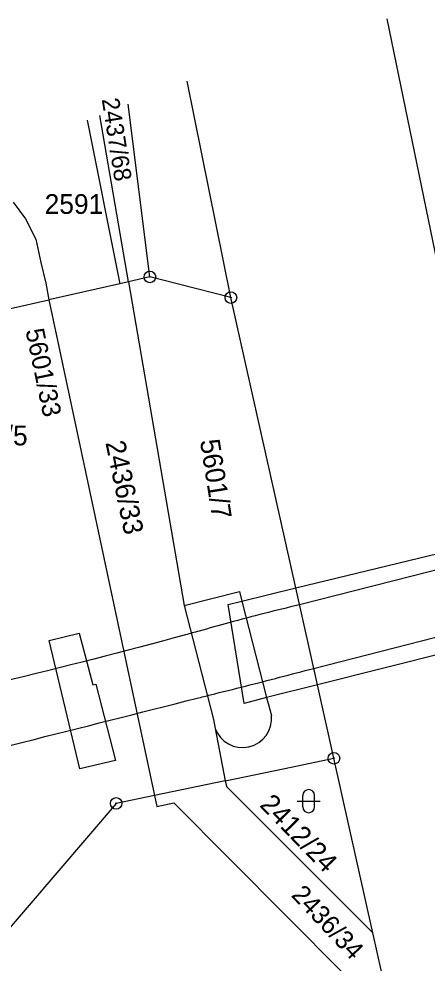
# Model space of a CAD drawing. Extents: x -825057 to -819383, y -1071633 to -1067888.
# Drawn here: x -820420.8 to -820385.6, y -1069607.9 to -1069526.4 of the extents above; entities that cross this region are included whole.
import ezdxf

# ---------------------------------------------------------------- set-up
doc = ezdxf.new("R2010")
doc.units = 0
for name, color, linetype in [('Vrstva 1', 7, 'Continuous'), ('Vrstva 10', 7, 'Continuous'), ('Vrstva 13', 7, 'Continuous'), ('Vrstva 16', 7, 'Continuous'), ('Vrstva 17', 7, 'Continuous'), ('Vrstva 18', 7, 'Continuous'), ('Vrstva 24', 7, 'Continuous'), ('Vrstva 25', 7, 'Continuous'), ('Vrstva 4', 7, 'Continuous')]:
    doc.layers.add(name, color=color, linetype=linetype)

msp = doc.modelspace()

# ---------------------------------------------------------------- linework, layer by layer
at = {"layer": 'Vrstva 1'}
for p, q in [((-820389.08, -1069526.4), (-820383.05, -1069555.68)), ((-820409.51, -1069548.66), (-820411.37, -1069533.75)), ((-820414.91, -1069535.15), (-820412.1, -1069549.25)), ((-820411.36, -1069549.08), (-820413.84, -1069534.72)), ((-820421.32, -1069542.21), (-820420.23, -1069543.65)), ((-820420.23, -1069543.65), (-820419.58, -1069544.95)), ((-820420.23, -1069543.65), (-820419.36, -1069545.39)), ((-820419.36, -1069545.39), (-820418.93, -1069547.42)), ((-820418.93, -1069547.42), (-820418.49, -1069549.19)), ((-820418.49, -1069549.19), (-820418.24, -1069550.64)), ((-820412.1, -1069549.25), (-820418.24, -1069550.64)), ((-820411.36, -1069549.08), (-820412.1, -1069549.25)), ((-820409.51, -1069548.66), (-820411.36, -1069549.08)), ((-820411.36, -1069549.08), (-820406.55, -1069577.01)), ((-820407.04, -1069549.29), (-820409.51, -1069548.66)), ((-820402.52, -1069550.44), (-820407.04, -1069549.29)), ((-820421.54, -1069551.39), (-820418.24, -1069550.64)), ((-820418.24, -1069550.64), (-820409.12, -1069593.39)), ((-820406.55, -1069577.01), (-820404.03, -1069586.83)), ((-820404.03, -1069586.83), (-820403.88, -1069587.6)), ((-820403.88, -1069587.6), (-820403.01, -1069592.12)), ((-820397.87, -1069591.06), (-820393.63, -1069590.18)), ((-820403.01, -1069592.12), (-820397.87, -1069591.06)), ((-820403.01, -1069592.12), (-820409.12, -1069593.39)), ((-820403.01, -1069592.12), (-820402.91, -1069592.61)), ((-820402.91, -1069592.61), (-820390.28, -1069605.24)), ((-820412.42, -1069594.07), (-820423.46, -1069606.97)), ((-820409.12, -1069593.39), (-820412.42, -1069594.07)), ((-820409.12, -1069593.39), (-820408.91, -1069594.35)), ((-820408.91, -1069594.35), (-820407.44, -1069594.03)), ((-820407.44, -1069594.03), (-820392.85, -1069608.7))]:
    msp.add_line(p, q, dxfattribs=at)
at = {"layer": 'Vrstva 10'}
for p, q in [((-820272.75, -1069545.33), (-820396.61, -1069576.94)), ((-820395.38, -1069582.43), (-820271.07, -1069550.51))]:
    msp.add_line(p, q, dxfattribs=at)
for points in [[(-820396.61, -1069576.94), (-820402.69, -1069578.49), (-820405.27, -1069579.21), (-820406.43, -1069579.53), (-820438.24, -1069587.5), (-820457.43, -1069592.39), (-820477.68, -1069597.79), (-820496.15, -1069603.16), (-820515.37, -1069609.41), (-820535.3, -1069616.98), (-820554.11, -1069625.3), (-820571.83, -1069634.26), (-820585.28, -1069641.81), (-820606.27, -1069655.04), (-820628.29, -1069671.01), (-820647.93, -1069687.34), (-820667.41, -1069705.6), (-820680.13, -1069718.49), (-820694.73, -1069734.03), (-820703.98, -1069744.22)], [(-820699.99, -1069747.07), (-820686.76, -1069732.45), (-820676.49, -1069721.48), (-820664.13, -1069708.83), (-820651.61, -1069696.85), (-820636.83, -1069683.83), (-820625.37, -1069674.56), (-820604.01, -1069659.07), (-820586.04, -1069647.64), (-820569.6, -1069638.45), (-820551.99, -1069629.79), (-820532.99, -1069621.67), (-820513.48, -1069614.48), (-820494.57, -1069608.43), (-820474.72, -1069602.78), (-820455.51, -1069597.69), (-820435.43, -1069592.58), (-820405.44, -1069585), (-820404.29, -1069584.71), (-820401.25, -1069583.95), (-820395.38, -1069582.43)]]:
    msp.add_spline(points, degree=3, dxfattribs=at)
at = {"layer": 'Vrstva 13'}
for p, q in [((-820402.52, -1069550.44), (-820406.29, -1069531.76)), ((-820396.93, -1069575.49), (-820402.52, -1069550.44)), ((-820395.06, -1069583.85), (-820396.93, -1069575.49)), ((-820393.63, -1069590.18), (-820395.06, -1069583.85)), ((-820390.28, -1069605.24), (-820393.63, -1069590.18)), ((-820389.54, -1069608.56), (-820390.28, -1069605.24))]:
    msp.add_line(p, q, dxfattribs=at)
at = {"layer": 'Vrstva 24'}
for centre, radius in [((-820409.51, -1069548.66), 0.5), ((-820409.51, -1069548.66), 0.0327), ((-820402.52, -1069550.44), 0.5), ((-820402.52, -1069550.44), 0.5), ((-820402.52, -1069550.44), 0.0327), ((-820402.52, -1069550.44), 0.0327), ((-820393.63, -1069590.18), 0.5), ((-820393.63, -1069590.18), 0.5), ((-820393.63, -1069590.18), 0.0327), ((-820393.63, -1069590.18), 0.0327), ((-820412.42, -1069594.07), 0.5), ((-820412.42, -1069594.07), 0.0327)]:
    msp.add_circle(centre, radius, dxfattribs=at)
at = {"layer": 'Vrstva 25'}
for p, q in [((-820396.81, -1069593.88), (-820394.81, -1069593.88)), ((-820396.31, -1069594.38), (-820396.31, -1069593.38)), ((-820395.31, -1069594.38), (-820395.31, -1069593.38))]:
    msp.add_line(p, q, dxfattribs=at)
for centre, start, end in [((-820395.81, -1069593.38), 0, 180), ((-820395.81, -1069594.38), 180, 0)]:
    msp.add_arc(centre, 0.5, start, end, dxfattribs=at)
at = {"layer": 'Vrstva 4'}
for p, q in [((-820396.93, -1069575.49), (-820379.33, -1069571.23)), ((-820406.55, -1069577.01), (-820401.79, -1069575.79)), ((-820401.79, -1069575.79), (-820401.57, -1069576.62)), ((-820401.57, -1069576.62), (-820396.93, -1069575.49)), ((-820402.75, -1069576.92), (-820401.57, -1069576.62)), ((-820401.38, -1069585.45), (-820402.75, -1069576.92)), ((-820401.57, -1069576.62), (-820399.44, -1069584.95)), ((-820418.19, -1069580.01), (-820415.61, -1069579.4)), ((-820415.61, -1069579.4), (-820414.44, -1069583.86)), ((-820377.38, -1069579.39), (-820395.06, -1069583.85)), ((-820415.54, -1069591.1), (-820418.19, -1069580.01)), ((-820414.44, -1069583.86), (-820414.16, -1069583.78)), ((-820414.16, -1069583.78), (-820412.48, -1069590.37)), ((-820395.06, -1069583.85), (-820399.44, -1069584.95)), ((-820399.44, -1069584.95), (-820401.38, -1069585.45)), ((-820399.44, -1069584.95), (-820399.03, -1069586.49)), ((-820412.48, -1069590.37), (-820415.54, -1069591.1))]:
    msp.add_line(p, q, dxfattribs=at)
msp.add_arc((-820401.524, -1069586.745), 2.507, 199.94961, 5.83246, dxfattribs=at)

# ---------------------------------------------------------------- texts
at = {"layer": 'Vrstva 16'}
msp.add_text('5601/33', height=1.6, rotation=281.7, dxfattribs=at).set_placement((-820420.249, -1069553.27))
msp.add_text('5601/5', height=1.7, dxfattribs=at).set_placement((-820427.006, -1069563.19))
msp.add_text('5601/5', height=1.7, dxfattribs=at).set_placement((-820427.006, -1069563.19))
msp.add_text('5601/5', height=1.7, dxfattribs=at).set_placement((-820427.006, -1069563.19))
at = {"layer": 'Vrstva 17'}
msp.add_text('2591', height=1.7, dxfattribs=at).set_placement((-820418.589, -1069543.22))
msp.add_text('2591', height=1.7, dxfattribs=at).set_placement((-820418.589, -1069543.22))
msp.add_text('2591', height=1.7, dxfattribs=at).set_placement((-820418.589, -1069543.22))
at = {"layer": 'Vrstva 18'}
for s, height, rotation, p in [('2437/68', 1.5, 279, (-820413.668, -1069533.33)), ('2436/33', 1.7, 281.7, (-820413.351, -1069562.953)), ('5601/7', 1.7, 279, (-820405.196, -1069562.781)), ('2412/24', 1.7, 314.1, (-820400.117, -1069594.271)), ('2436/34', 1.6, 313.2, (-820397.382, -1069602.04))]:
    msp.add_text(s, height=height, rotation=rotation, dxfattribs=at).set_placement(p)

doc.saveas('drawing.dxf')
